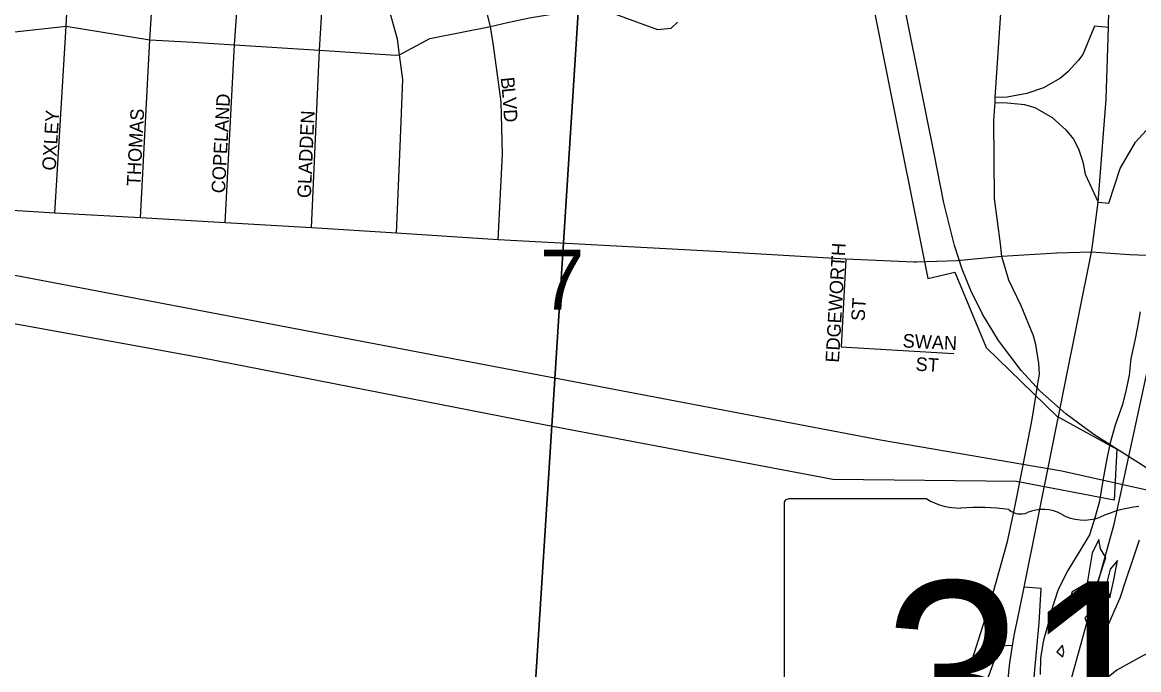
# Model space of a CAD drawing. Extents: x 0 to 34, y -6.2 to 22.
# Drawn here: x 4.825 to 5.605, y 18.6 to 19.053 of the extents above; entities that cross this region are included whole.
import ezdxf

# ---------------------------------------------------------------- set-up
doc = ezdxf.new("R2010")
doc.units = 0
for name, color, linetype in [('GM_X_City_Street', 7, 'Continuous'), ('GM_X_City_Street_Text', 7, 'Continuous'), ('GM_X_Corporation', 7, 'Continuous'), ('GM_X_Interchange_Ramps', 7, 'Continuous'), ('GM_X_Major_River', 7, 'Continuous'), ('GM_X_Rail_Line', 7, 'Continuous'), ('GM_X_Section', 7, 'Continuous'), ('GM_X_Section_Text', 7, 'Continuous'), ('GM_X_State_Route', 7, 'Continuous'), ('GM_X_State_Shield', 7, 'Continuous'), ('GM_X_Township', 7, 'Continuous')]:
    doc.layers.add(name, color=color, linetype=linetype)

msp = doc.modelspace()

# ---------------------------------------------------------------- linework, layer by layer
at = {"layer": 'GM_X_City_Street'}
for points in [[(4.84737, 18.91938), (4.85518, 19.05009), (4.86416, 19.21593), (4.86759, 19.28314), (4.85871, 19.32588), (4.84737, 19.38901), (4.84572, 19.41187), (4.84276, 19.46924), (4.84457, 19.51347), (4.84788, 19.58071)], [(5.50453, 18.99669), (5.50453, 19.00022), (5.5089, 19.06607), (5.51289, 19.10116), (5.51511, 19.13159), (5.51577, 19.16622), (5.51444, 19.18931), (5.512, 19.21906), (5.50606, 19.25583), (5.4918, 19.35872), (5.48996, 19.38167), (5.49165, 19.41267), (5.49869, 19.45993), (5.5039, 19.50934), (5.50934, 19.57319), (5.50877, 19.58327)], [(4.9664, 18.91247), (4.9728, 19.03691), (4.9845, 19.20072), (4.98612, 19.22359), (4.98814, 19.24376), (4.99599, 19.26012), (4.99971, 19.26635), (5.00667, 19.27804), (5.0144, 19.28757)], [(4.90705, 18.91609), (4.91372, 19.04043), (4.9246, 19.21268)], [(5.08603, 18.90525), (5.08866, 18.96592), (5.09058, 19.0128), (5.08826, 19.03007), (5.0868, 19.04088), (5.08004, 19.06512), (5.05254, 19.11446), (4.9845, 19.20072)], [(5.02674, 18.90902), (5.03237, 19.03317), (5.03472, 19.07558), (5.03674, 19.09575), (5.03894, 19.10186), (5.04345, 19.10533), (5.05254, 19.11446)], [(5.14994, 18.90112), (5.08603, 18.90525), (5.02674, 18.90902), (4.9664, 18.91247), (4.90705, 18.91609), (4.84737, 18.91938), (4.7877, 18.92315), (4.72818, 18.92661), (4.70878, 18.92776), (4.69908, 18.93006), (4.6925, 18.93236), (4.68527, 18.93598), (4.66785, 18.94585), (4.62198, 18.97116), (4.55276, 19.00782), (4.46332, 19.05452), (4.45329, 19.05944), (4.44689, 19.06224), (4.4385, 19.06471), (4.37554, 19.06947), (4.29651, 19.07423)], [(5.15721, 18.90065), (5.16018, 18.96049), (5.15913, 18.99722), (5.15381, 19.03653), (5.15168, 19.04985), (5.14839, 19.0635)], [(5.16369, 19.05255), (5.16483, 19.05281), (5.17897, 19.05577), (5.20413, 19.06004), (5.23914, 19.05839), (5.26859, 19.0477), (5.27808, 19.04858), (5.28258, 19.05281)], [(4.70717, 19.05222), (4.73315, 19.05125), (4.79092, 19.04732), (4.81715, 19.04589), (4.85518, 19.05009), (4.91372, 19.04043), (4.94406, 19.03872), (4.9728, 19.03691), (5.03237, 19.03317), (5.08543, 19.02984), (5.08826, 19.03007), (5.10943, 19.04146), (5.15168, 19.04985), (5.16369, 19.05255)], [(5.44942, 18.88518), (5.44762, 18.88513), (5.40001, 18.88709), (5.30894, 18.89247), (5.15721, 18.90065), (5.14994, 18.90112)], [(5.40001, 18.88709), (5.39677, 18.826)], [(5.50924, 18.88911), (5.47795, 18.88603), (5.44942, 18.88518)], [(5.51695, 18.70829), (5.51906, 18.71845), (5.53008, 18.77394), (5.53557, 18.80696), (5.53507, 18.81417), (5.53285, 18.82758), (5.53124, 18.83368), (5.52262, 18.85447), (5.51403, 18.87252), (5.50924, 18.88911)], [(5.39677, 18.826), (5.43623, 18.82362)], [(5.43623, 18.82362), (5.47569, 18.82124)], [(5.15969, 18.46671), (5.16303, 18.466), (5.17536, 18.46304), (5.19608, 18.45778), (5.2265, 18.45202), (5.2551, 18.44775), (5.27548, 18.44635), (5.29817, 18.4466), (5.31428, 18.44824), (5.32486, 18.44984), (5.34026, 18.4535), (5.35588, 18.45926), (5.37774, 18.46994), (5.39336, 18.47981), (5.41255, 18.496), (5.43658, 18.51788), (5.45413, 18.53625), (5.47319, 18.56815), (5.48249, 18.58878), (5.50185, 18.64975), (5.51311, 18.68982), (5.51695, 18.70829)]]:
    msp.add_lwpolyline(points, dxfattribs=at)
at = {"layer": 'GM_X_Corporation'}
msp.add_lwpolyline([(4.71375, 19.58418), (5.32348, 19.55244), (5.39824, 19.16936), (5.45733, 18.87379), (5.47637, 18.87813), (5.49814, 18.82544), (5.54769, 18.77737), (5.58957, 18.75448), (5.5876, 18.71873), (5.51933, 18.73178), (5.39106, 18.73316), (5.19023, 18.77116), (4.94964, 18.81836), (4.63019, 18.87633)], dxfattribs=at)
msp.add_lwpolyline([(4.71375, 19.58418), (5.32348, 19.55244), (5.39824, 19.16936), (5.45733, 18.87379), (5.47637, 18.87813), (5.49814, 18.82544), (5.54769, 18.77737), (5.58957, 18.75448), (5.5876, 18.71873), (5.51933, 18.73178), (5.39106, 18.73316), (5.19023, 18.77116), (4.94964, 18.81836), (4.63019, 18.87633)], dxfattribs=at)
at = {"layer": 'GM_X_Interchange_Ramps'}
for points in [[(5.58375, 19.04897), (5.57387, 19.04996), (5.56569, 19.03017), (5.56284, 19.02629), (5.55537, 19.01811), (5.55004, 19.01367), (5.53831, 19.00691), (5.52667, 19.00288), (5.51297, 19.00035), (5.50453, 19.00022)], [(5.57657, 18.92699), (5.58399, 18.92621), (5.59195, 18.95061), (5.60256, 18.96903), (5.61253, 18.97986), (5.62466, 18.99113), (5.63218, 18.9961), (5.63858, 18.99997), (5.65422, 19.00672), (5.66917, 19.00993), (5.67489, 19.01065), (5.68029, 19.01054), (5.68601, 19.00952), (5.69173, 19.00789), (5.69907, 19.00524), (5.70366, 19.00319), (5.71631, 18.99288), (5.72459, 18.98166), (5.72892, 18.97344), (5.73198, 18.96446), (5.73208, 18.9583), (5.72853, 18.89072), (5.72828, 18.8849)], [(5.41146, 18.39954), (5.41891, 18.40628), (5.4438, 18.4271), (5.46416, 18.44293), (5.48182, 18.45832), (5.49539, 18.47371), (5.50671, 18.49), (5.51476, 18.50298), (5.51827, 18.51315), (5.5191, 18.51556), (5.52316, 18.5273), (5.52709, 18.54665), (5.52933, 18.5606), (5.53205, 18.59771), (5.53522, 18.63301), (5.53658, 18.657), (5.52486, 18.65788)], [(5.66473, 18.62299), (5.65922, 18.63482), (5.63478, 18.62396), (5.60672, 18.60948), (5.58952, 18.59997), (5.57414, 18.58776), (5.55906, 18.57201), (5.54699, 18.55743), (5.53839, 18.5434), (5.53325, 18.53226), (5.52999, 18.52453), (5.52616, 18.51353), (5.52275, 18.49858), (5.52123, 18.49194), (5.51892, 18.48186), (5.51802, 18.4538), (5.523, 18.42619), (5.53499, 18.39021), (5.53567, 18.38817), (5.56583, 18.32231), (5.60672, 18.2343), (5.61521, 18.23758)], [(5.51662, 18.61712), (5.50761, 18.61672), (5.49946, 18.59454), (5.49132, 18.57101), (5.47819, 18.53843), (5.46688, 18.51036), (5.45195, 18.48683), (5.43475, 18.46059), (5.41438, 18.43479), (5.42131, 18.42704)]]:
    msp.add_lwpolyline(points, dxfattribs=at)
at = {"layer": 'GM_X_Major_River'}
for points in [[(5.6059, 18.85042), (5.60395, 18.8398), (5.60199, 18.83033), (5.59927, 18.81782), (5.59806, 18.80606), (5.59611, 18.79621), (5.59339, 18.7856), (5.58838, 18.77121), (5.58452, 18.75795), (5.58256, 18.74772), (5.57982, 18.73255), (5.57746, 18.71815), (5.57436, 18.70716), (5.5705, 18.69466), (5.56285, 18.68218), (5.55482, 18.66895), (5.5483, 18.65571), (5.54328, 18.64056), (5.54095, 18.63071), (5.53824, 18.62086), (5.53627, 18.60872), (5.53583, 18.59696)], [(5.55464, 18.63897), (5.56491, 18.64574), (5.57175, 18.64874), (5.57637, 18.66237), (5.58177, 18.67866), (5.57802, 18.68475), (5.57692, 18.69121)], [(5.57692, 18.69121), (5.57232, 18.68175), (5.56879, 18.6609), (5.55814, 18.65451), (5.55464, 18.63897)], [(5.56911, 18.58842), (5.57184, 18.6013), (5.57569, 18.61153), (5.5807, 18.62516), (5.58569, 18.63689), (5.59183, 18.65052), (5.59608, 18.6634), (5.6007, 18.67703), (5.60533, 18.69104)], [(5.59009, 18.67671), (5.58476, 18.67067), (5.58204, 18.6593), (5.58463, 18.65056)], [(5.58463, 18.65056), (5.58736, 18.66307), (5.59009, 18.67671)], [(5.57208, 18.64153), (5.56713, 18.63662), (5.57049, 18.62825)], [(5.57049, 18.62825), (5.57318, 18.63469), (5.57208, 18.64153)], [(5.55148, 18.61736), (5.54766, 18.61283), (5.55181, 18.60939)], [(5.55181, 18.60939), (5.55259, 18.6128), (5.55148, 18.61736)]]:
    msp.add_lwpolyline(points, dxfattribs=at)
at = {"layer": 'GM_X_Rail_Line'}
for points in [[(5.64517, 18.71967), (5.63403, 18.72622), (5.57338, 18.76459), (5.5538, 18.77907), (5.53597, 18.79499), (5.5226, 18.80948), (5.50684, 18.83033), (5.49553, 18.8488), (5.48742, 18.86535), (5.48153, 18.88016), (5.47595, 18.89671), (5.46863, 18.92648), (5.46179, 18.96102), (5.42135, 19.16224), (5.41803, 19.17928), (5.39525, 19.29166), (5.38649, 19.33368), (5.31231, 19.70061), (5.30783, 19.72433)], [(4.66612, 18.90501), (5.42425, 18.76083), (5.55097, 18.73931), (5.61258, 18.72544), (5.62948, 18.72221), (5.64517, 18.71967)]]:
    msp.add_lwpolyline(points, dxfattribs=at)
at = {"layer": 'GM_X_Section'}
for points in [[(4.71794, 19.38931), (5.23224, 19.35957), (5.17024, 18.38679), (4.97661, 18.40016), (4.96149, 18.40555), (4.94372, 18.41097), (4.915, 18.42251), (4.89649, 18.43134), (4.89237, 18.43704), (4.88678, 18.45299), (4.88341, 18.45907), (4.87171, 18.46596), (4.85851, 18.47551), (4.84495, 18.48809), (4.8265, 18.50677), (4.80881, 18.52469), (4.78244, 18.54682), (4.76999, 18.55599), (4.74885, 18.56786), (4.72015, 18.58167), (4.68881, 18.59815), (4.66994, 18.61077)], [(5.23224, 19.35957), (5.74527, 19.32804), (5.6843, 18.35147), (5.42283, 18.36869), (5.41773, 18.36902), (5.19797, 18.38488), (5.17024, 18.38679)]]:
    msp.add_lwpolyline(points, close=True, dxfattribs=at)
at = {"layer": 'GM_X_State_Route'}
for points in [[(5.57253, 18.8968), (5.57657, 18.92699), (5.58198, 18.99893), (5.58375, 19.04897), (5.58407, 19.07395), (5.58202, 19.10613), (5.57669, 19.1371), (5.56971, 19.17839), (5.56346, 19.2108), (5.55907, 19.26334), (5.54984, 19.30906), (5.54579, 19.32856)], [(5.50813, 18.8978), (5.50408, 18.92957), (5.50352, 18.98418), (5.5043, 18.99383)], [(5.5043, 18.99383), (5.50453, 18.99669), (5.513, 18.99636), (5.52493, 18.99525), (5.53221, 18.99314), (5.54443, 18.98629), (5.55396, 18.97764), (5.55933, 18.97104), (5.56279, 18.96426), (5.56583, 18.95512), (5.56747, 18.94649), (5.57657, 18.92699)], [(5.57182, 18.89208), (5.54769, 18.8913), (5.50924, 18.88911), (5.50813, 18.8978)], [(5.51782, 18.51461), (5.51347, 18.54034), (5.51247, 18.55777), (5.51225, 18.58078), (5.51466, 18.60511), (5.51662, 18.61712), (5.51795, 18.62528), (5.52145, 18.64193), (5.52486, 18.65788), (5.5719, 18.89208), (5.57253, 18.8968)], [(5.83124, 18.8428), (5.81834, 18.85321), (5.80843, 18.86078), (5.79396, 18.86883), (5.78511, 18.87325), (5.77275, 18.87771), (5.76179, 18.88074), (5.73696, 18.88436), (5.72828, 18.8849), (5.62821, 18.88915), (5.59837, 18.8903), (5.5719, 18.89208), (5.57182, 18.89208)]]:
    msp.add_lwpolyline(points, dxfattribs=at)
at = {"layer": 'GM_X_State_Shield'}
for p, q in [((5.45678, 18.71965), (5.36026, 18.71965)), ((5.35701, 18.71621), (5.35701, 18.51609))]:
    msp.add_line(p, q, dxfattribs=at)
for centre, major_axis, start_param, end_param in [((5.36079, 18.71664), (0.00382, 0), 1.712693, 3.28349), ((5.47976, 18.74288), (0.03703, 0), 4.042523, 4.731795), ((5.49204, 18.6073), (0.13295, 0), 1.404758, 1.657858), ((5.52223, 18.71767), (0.01068, 0), 3.836095, 5.185415), ((5.53791, 18.69454), (0.02221, 0), 0.950623, 2.079405), ((5.61378, 18.65853), (0.07032, 0), 1.699011, 2.107814), ((5.56658, 18.72627), (0.02672, 0), 4.081561, 5.145723)]:
    msp.add_ellipse(centre, major_axis=major_axis, ratio=0.8, start_param=start_param, end_param=end_param, dxfattribs=at)
at = {"layer": 'GM_X_Township'}
msp.add_lwpolyline([(5.55748, 18.59263), (5.58758, 18.70211), (5.62821, 18.88915)], dxfattribs=at)

# ---------------------------------------------------------------- texts
at = {"layer": 'GM_X_City_Street_Text'}
for s, rotation, p in [('B', 275.66711, (5.15885, 19.01396)), ('L', 275.58282, (5.15959, 19.0065)), ('COPELAND', 86.90458, (4.96613, 18.93305)), ('V', 274.09029, (5.16023, 18.99993)), ('OXLEY', 86.34521, (4.8478, 18.94889)), ('THOMAS', 87.09065, (4.90697, 18.93804)), ('D', 273.19318, (5.16082, 18.99166)), ('GLADDEN', 87.43443, (5.02613, 18.92969)), ('EDGEWORTH', 86.7474, (5.3953, 18.81471)), ('ST', 86.4126, (5.41322, 18.84371)), ('SWAN', 357.20885, (5.43966, 18.82556)), ('ST', 356.42537, (5.44867, 18.8093))]:
    msp.add_text(s, height=0.00947, rotation=rotation, dxfattribs=at).set_placement(p)
at = {"layer": 'GM_X_Section_Text'}
msp.add_text('7', height=0.04186, rotation=0.00001, dxfattribs=at).set_placement((5.18624, 18.85186))
at = {"layer": 'GM_X_State_Shield'}
msp.add_text('315', height=0.131836, dxfattribs=at).set_placement((5.4261, 18.5302))

doc.saveas('drawing.dxf')
